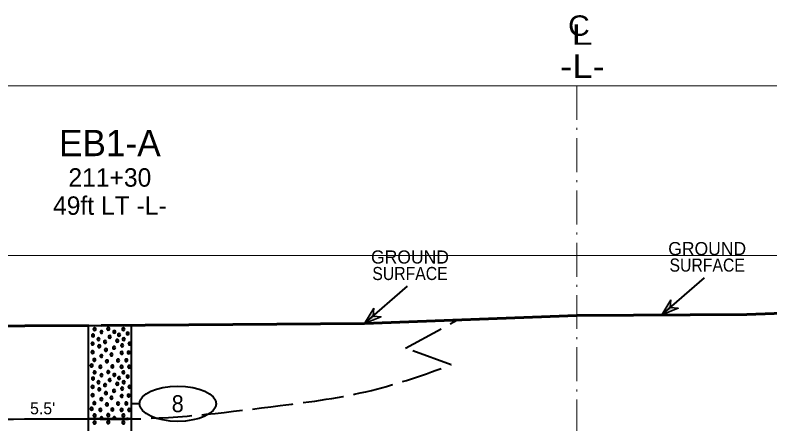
# Model space of a CAD drawing. Extents: x -582 to 653, y -817 to -3.
# Drawn here: x -29.8 to 14.65, y -494.04 to -469.97 of the extents above; entities that cross this region are included whole.
import ezdxf
from ezdxf.enums import TextEntityAlignment as Align

# ---------------------------------------------------------------- set-up
doc = ezdxf.new("R2010")
doc.units = 0
doc.header["$LTSCALE"] = 0.4
doc.linetypes.add('DOT_DASHED', pattern=[7.7, 5, -1.2, 0.3, -1.2])
doc.linetypes.add('LONG_DASHED', pattern=[7.5, 6, -1.5])
for name, color, linetype, lineweight in [('10', 7, 'Continuous', 35), ('26', 7, 'LONG_DASHED', 40), ('27', 7, 'Continuous', 40), ('7', 7, 'Continuous', 13)]:
    doc.layers.add(name, color=color, linetype=linetype, lineweight=lineweight)

msp = doc.modelspace()

# ---------------------------------------------------------------- hatches: boundary and pattern name
at = {"layer": '10'}
for points in [[(8.8165, -486.7304), (8.2789, -487.628), (9.2473, -487.2326), (8.7809, -487.1968)], [(-8.6835, -487.2255), (-9.2211, -488.1231), (-8.2527, -487.7277), (-8.7191, -487.6919)]]:
    msp.add_hatch(color=256, dxfattribs=at).paths.add_polyline_path(points)

# ---------------------------------------------------------------- linework, layer by layer
for points in [[(8.8165, -486.7304), (8.2789, -487.628), (9.2473, -487.2326), (8.7809, -487.1968)], [(-8.6835, -487.2255), (-9.2211, -488.1231), (-8.2527, -487.7277), (-8.7191, -487.6919)]]:
    msp.add_lwpolyline(points, close=True, dxfattribs=at)
at = {"layer": '26', "linetype": 'Continuous', "lineweight": 60}
for points in [[(-9.2213, -488.1228), (3.2787, -487.6628), (13.2787, -487.5928), (20.7787, -487.3328), (27.2787, -487.2128), (33.2787, -486.9428), (43.2787, -486.7528)], [(-24.7213, -488.2528), (-9.2213, -488.1228), (3.2787, -487.6628), (13.2787, -487.5928)], [(-41.7213, -488.2328), (-36.7213, -488.3028), (-25.4713, -488.256)]]:
    msp.add_lwpolyline(points, dxfattribs=at)
at = {"layer": '26'}
msp.add_lwpolyline([(-4.1274, -490.5739), (-6.817, -489.577), (-3.7572, -487.9217)], dxfattribs=at)
msp.add_spline([(-39.7899, -493.8636), (-29.2387, -493.7528), (-25.4713, -493.7528), (-22.9713, -493.7528), (-14.1886, -492.9664), (-8.8094, -492.0692), (-4.1274, -490.5739)], degree=3, dxfattribs=at)
at = {"layer": '27'}
for p, q in [((8.2787, -487.6278), (10.7991, -485.4455)), ((-9.2213, -488.1228), (-6.7009, -485.9405)), ((-22.4714, -492.8528), (-22.9714, -492.8528)), ((-29.2387, -493.7528), (-25.4713, -493.7528))]:
    msp.add_line(p, q, dxfattribs=at)
for points in [[(-25.4713, -488.2528), (-22.9713, -488.2528), (-22.9713, -493.7528), (-25.4713, -493.7528)], [(-25.0394, -488.4655), (-25.0496, -488.4274), (-25.0775, -488.3995), (-25.1156, -488.3893), (-25.1537, -488.3995), (-25.1816, -488.4274), (-25.1918, -488.4655), (-25.1816, -488.5036), (-25.1537, -488.5314), (-25.1156, -488.5417), (-25.0775, -488.5314), (-25.0496, -488.5036)], [(-24.2384, -488.4459), (-24.2487, -488.4078), (-24.2765, -488.3799), (-24.3146, -488.3697), (-24.3527, -488.3799), (-24.3806, -488.4078), (-24.3908, -488.4459), (-24.3806, -488.484), (-24.3527, -488.5119), (-24.3146, -488.5221), (-24.2765, -488.5119), (-24.2487, -488.484)], [(-23.3448, -488.4655), (-23.355, -488.4274), (-23.3829, -488.3995), (-23.421, -488.3893), (-23.4591, -488.3995), (-23.487, -488.4274), (-23.4972, -488.4655), (-23.487, -488.5036), (-23.4591, -488.5315), (-23.421, -488.5417), (-23.3829, -488.5315), (-23.355, -488.5036)], [(-25.1356, -488.8333), (-25.1458, -488.7952), (-25.1737, -488.7673), (-25.2118, -488.7571), (-25.2499, -488.7673), (-25.2778, -488.7952), (-25.288, -488.8333), (-25.2778, -488.8714), (-25.2499, -488.8993), (-25.2118, -488.9095), (-25.1737, -488.8993), (-25.1458, -488.8714)], [(-24.6345, -488.6307), (-24.6447, -488.5926), (-24.6726, -488.5647), (-24.7107, -488.5545), (-24.7488, -488.5647), (-24.7767, -488.5926), (-24.7869, -488.6307), (-24.7767, -488.6688), (-24.7488, -488.6967), (-24.7107, -488.7069), (-24.6726, -488.6967), (-24.6447, -488.6688)], [(-24.1495, -488.9165), (-24.1597, -488.8784), (-24.1876, -488.8505), (-24.2257, -488.8403), (-24.2638, -488.8505), (-24.2917, -488.8784), (-24.3019, -488.9165), (-24.2917, -488.9546), (-24.2638, -488.9825), (-24.2257, -488.9927), (-24.1876, -488.9825), (-24.1597, -488.9546)], [(-23.8794, -488.6217), (-23.8896, -488.5836), (-23.9175, -488.5557), (-23.9556, -488.5455), (-23.9937, -488.5557), (-24.0216, -488.5836), (-24.0318, -488.6217), (-24.0216, -488.6598), (-23.9937, -488.6877), (-23.9556, -488.6979), (-23.9175, -488.6877), (-23.8896, -488.6598)], [(-23.6012, -488.799), (-23.6114, -488.7609), (-23.6393, -488.733), (-23.6774, -488.7228), (-23.7155, -488.733), (-23.7434, -488.7609), (-23.7536, -488.799), (-23.7434, -488.8371), (-23.7155, -488.865), (-23.6774, -488.8752), (-23.6393, -488.865), (-23.6114, -488.8371)], [(-23.0939, -488.7176), (-23.1041, -488.6795), (-23.132, -488.6516), (-23.1701, -488.6414), (-23.2082, -488.6516), (-23.2361, -488.6795), (-23.2463, -488.7176), (-23.2361, -488.7557), (-23.2082, -488.7836), (-23.1701, -488.7938), (-23.132, -488.7836), (-23.1041, -488.7557)], [(-25.1585, -489.3177), (-25.1687, -489.2796), (-25.1966, -489.2517), (-25.2347, -489.2415), (-25.2728, -489.2517), (-25.3007, -489.2796), (-25.3109, -489.3177), (-25.3007, -489.3558), (-25.2728, -489.3837), (-25.2347, -489.3939), (-25.1966, -489.3837), (-25.1687, -489.3558)], [(-24.8127, -489.052), (-24.8229, -489.0139), (-24.8508, -488.986), (-24.8889, -488.9758), (-24.927, -488.986), (-24.9549, -489.0139), (-24.9651, -489.052), (-24.9549, -489.0901), (-24.927, -489.118), (-24.8889, -489.1282), (-24.8508, -489.118), (-24.8229, -489.0901)], [(-24.4211, -489.2134), (-24.4314, -489.1753), (-24.4592, -489.1474), (-24.4973, -489.1372), (-24.5354, -489.1474), (-24.5633, -489.1753), (-24.5735, -489.2134), (-24.5633, -489.2515), (-24.5354, -489.2794), (-24.4973, -489.2896), (-24.4592, -489.2794), (-24.4314, -489.2515)], [(-23.7054, -489.1448), (-23.7156, -489.1067), (-23.7435, -489.0788), (-23.7816, -489.0686), (-23.8197, -489.0788), (-23.8476, -489.1067), (-23.8578, -489.1448), (-23.8476, -489.1829), (-23.8197, -489.2108), (-23.7816, -489.221), (-23.7435, -489.2108), (-23.7156, -489.1829)], [(-23.324, -489.052), (-23.3342, -489.0139), (-23.3621, -488.986), (-23.4002, -488.9758), (-23.4383, -488.986), (-23.4662, -489.0139), (-23.4764, -489.052), (-23.4662, -489.0901), (-23.4383, -489.118), (-23.4002, -489.1282), (-23.3621, -489.118), (-23.3342, -489.0901)], [(-22.9783, -489.3177), (-22.9885, -489.2796), (-23.0164, -489.2517), (-23.0545, -489.2415), (-23.0926, -489.2517), (-23.1204, -489.2796), (-23.1307, -489.3177), (-23.1204, -489.3558), (-23.0926, -489.3837), (-23.0545, -489.3939), (-23.0164, -489.3837), (-22.9885, -489.3558)], [(-25.1585, -489.8135), (-25.1687, -489.7754), (-25.1966, -489.7475), (-25.2347, -489.7373), (-25.2728, -489.7475), (-25.3007, -489.7754), (-25.3109, -489.8135), (-25.3007, -489.8516), (-25.2728, -489.8794), (-25.2347, -489.8897), (-25.1966, -489.8794), (-25.1687, -489.8516)], [(-24.7669, -489.4677), (-24.7771, -489.4296), (-24.805, -489.4017), (-24.8431, -489.3915), (-24.8812, -489.4017), (-24.9091, -489.4296), (-24.9193, -489.4677), (-24.9091, -489.5058), (-24.8812, -489.5337), (-24.8431, -489.5439), (-24.805, -489.5337), (-24.7771, -489.5058)], [(-24.3728, -489.6863), (-24.383, -489.6482), (-24.4109, -489.6203), (-24.449, -489.6101), (-24.4871, -489.6203), (-24.515, -489.6482), (-24.5252, -489.6863), (-24.515, -489.7244), (-24.4871, -489.7523), (-24.449, -489.7625), (-24.4109, -489.7523), (-24.383, -489.7244)], [(-23.8948, -489.5554), (-23.905, -489.5173), (-23.9329, -489.4894), (-23.971, -489.4792), (-24.0091, -489.4894), (-24.037, -489.5173), (-24.0472, -489.5554), (-24.037, -489.5935), (-24.0091, -489.6214), (-23.971, -489.6316), (-23.9329, -489.6214), (-23.905, -489.5935)], [(-23.4168, -489.4219), (-23.4271, -489.3838), (-23.4549, -489.3559), (-23.493, -489.3457), (-23.5311, -489.3559), (-23.559, -489.3838), (-23.5692, -489.4219), (-23.559, -489.46), (-23.5311, -489.4879), (-23.493, -489.4981), (-23.4549, -489.4879), (-23.4271, -489.46)], [(-23.0355, -489.8363), (-23.0457, -489.7982), (-23.0736, -489.7704), (-23.1117, -489.7601), (-23.1498, -489.7704), (-23.1777, -489.7982), (-23.1879, -489.8363), (-23.1777, -489.8744), (-23.1498, -489.9023), (-23.1117, -489.9125), (-23.0736, -489.9023), (-23.0457, -489.8744)], [(-25.0555, -490.2762), (-25.0657, -490.2381), (-25.0936, -490.2102), (-25.1317, -490.2), (-25.1698, -490.2102), (-25.1977, -490.2381), (-25.2079, -490.2762), (-25.1977, -490.3143), (-25.1698, -490.3422), (-25.1317, -490.3524), (-25.0936, -490.3422), (-25.0657, -490.3143)], [(-24.6398, -490.0448), (-24.65, -490.0067), (-24.6779, -489.9788), (-24.716, -489.9686), (-24.7541, -489.9788), (-24.782, -490.0067), (-24.7922, -490.0448), (-24.782, -490.0829), (-24.7541, -490.1108), (-24.716, -490.121), (-24.6779, -490.1108), (-24.65, -490.0829)], [(-24.0449, -489.9609), (-24.0551, -489.9228), (-24.083, -489.8949), (-24.1211, -489.8847), (-24.1592, -489.8949), (-24.187, -489.9228), (-24.1973, -489.9609), (-24.187, -489.999), (-24.1592, -490.0269), (-24.1211, -490.0371), (-24.083, -490.0269), (-24.0551, -489.999)], [(-23.4397, -489.8605), (-23.4499, -489.8224), (-23.4778, -489.7945), (-23.5159, -489.7843), (-23.554, -489.7945), (-23.5819, -489.8224), (-23.5921, -489.8605), (-23.5819, -489.8986), (-23.554, -489.9265), (-23.5159, -489.9367), (-23.4778, -489.9265), (-23.4499, -489.8986)], [(-25.217, -490.6093), (-25.2272, -490.5712), (-25.2551, -490.5433), (-25.2932, -490.5331), (-25.3313, -490.5433), (-25.3592, -490.5712), (-25.3694, -490.6093), (-25.3592, -490.6474), (-25.3313, -490.6753), (-25.2932, -490.6855), (-25.2551, -490.6753), (-25.2272, -490.6474)], [(-24.6983, -490.6792), (-24.7085, -490.6411), (-24.7364, -490.6132), (-24.7745, -490.603), (-24.8126, -490.6132), (-24.8405, -490.6411), (-24.8507, -490.6792), (-24.8405, -490.7173), (-24.8126, -490.7452), (-24.7745, -490.7554), (-24.7364, -490.7452), (-24.7085, -490.7173)], [(-24.3169, -490.3563), (-24.3271, -490.3182), (-24.355, -490.2903), (-24.3931, -490.2801), (-24.4312, -490.2903), (-24.4591, -490.3182), (-24.4693, -490.3563), (-24.4591, -490.3944), (-24.4312, -490.4223), (-24.3931, -490.4325), (-24.355, -490.4223), (-24.3271, -490.3944)], [(-23.994, -490.6563), (-24.0042, -490.6182), (-24.0321, -490.5903), (-24.0702, -490.5801), (-24.1083, -490.5903), (-24.1362, -490.6182), (-24.1464, -490.6563), (-24.1362, -490.6944), (-24.1083, -490.7223), (-24.0702, -490.7325), (-24.0321, -490.7223), (-24.0042, -490.6944)], [(-23.6597, -490.3054), (-23.6699, -490.2673), (-23.6978, -490.2394), (-23.7359, -490.2292), (-23.774, -490.2394), (-23.8018, -490.2673), (-23.8121, -490.3054), (-23.8018, -490.3435), (-23.774, -490.3714), (-23.7359, -490.3816), (-23.6978, -490.3714), (-23.6699, -490.3435)], [(-23.4512, -490.6792), (-23.4614, -490.6411), (-23.4893, -490.6132), (-23.5274, -490.603), (-23.5655, -490.6132), (-23.5934, -490.6411), (-23.6036, -490.6792), (-23.5934, -490.7173), (-23.5655, -490.7452), (-23.5274, -490.7554), (-23.4893, -490.7452), (-23.4614, -490.7173)], [(-23.174, -490.2978), (-23.1842, -490.2597), (-23.2121, -490.2318), (-23.2502, -490.2216), (-23.2883, -490.2318), (-23.3162, -490.2597), (-23.3264, -490.2978), (-23.3162, -490.3359), (-23.2883, -490.3638), (-23.2502, -490.374), (-23.2121, -490.3638), (-23.1842, -490.3359)], [(-23.0011, -490.6792), (-23.0113, -490.6411), (-23.0392, -490.6132), (-23.0773, -490.603), (-23.1154, -490.6132), (-23.1433, -490.6411), (-23.1535, -490.6792), (-23.1433, -490.7173), (-23.1154, -490.7452), (-23.0773, -490.7554), (-23.0392, -490.7452), (-23.0113, -490.7173)], [(-25.0394, -491.0055), (-25.0496, -490.9674), (-25.0775, -490.9395), (-25.1156, -490.9293), (-25.1537, -490.9395), (-25.1816, -490.9674), (-25.1918, -491.0055), (-25.1816, -491.0436), (-25.1537, -491.0714), (-25.1156, -491.0817), (-25.0775, -491.0714), (-25.0496, -491.0436)], [(-24.6345, -491.1707), (-24.6447, -491.1326), (-24.6726, -491.1047), (-24.7107, -491.0945), (-24.7488, -491.1047), (-24.7767, -491.1326), (-24.7869, -491.1707), (-24.7767, -491.2088), (-24.7488, -491.2367), (-24.7107, -491.2469), (-24.6726, -491.2367), (-24.6447, -491.2088)], [(-24.2384, -490.9859), (-24.2487, -490.9478), (-24.2765, -490.9199), (-24.3146, -490.9097), (-24.3527, -490.9199), (-24.3806, -490.9478), (-24.3908, -490.9859), (-24.3806, -491.024), (-24.3527, -491.0519), (-24.3146, -491.0621), (-24.2765, -491.0519), (-24.2487, -491.024)], [(-23.8794, -491.1617), (-23.8896, -491.1236), (-23.9175, -491.0957), (-23.9556, -491.0855), (-23.9937, -491.0957), (-24.0216, -491.1236), (-24.0318, -491.1617), (-24.0216, -491.1998), (-23.9937, -491.2277), (-23.9556, -491.2379), (-23.9175, -491.2277), (-23.8896, -491.1998)], [(-23.3448, -491.0055), (-23.355, -490.9674), (-23.3829, -490.9395), (-23.421, -490.9293), (-23.4591, -490.9395), (-23.487, -490.9674), (-23.4972, -491.0055), (-23.487, -491.0436), (-23.4591, -491.0715), (-23.421, -491.0817), (-23.3829, -491.0715), (-23.355, -491.0436)], [(-25.1356, -491.3733), (-25.1458, -491.3352), (-25.1737, -491.3073), (-25.2118, -491.2971), (-25.2499, -491.3073), (-25.2778, -491.3352), (-25.288, -491.3733), (-25.2778, -491.4114), (-25.2499, -491.4393), (-25.2118, -491.4495), (-25.1737, -491.4393), (-25.1458, -491.4114)], [(-24.8127, -491.592), (-24.8229, -491.5539), (-24.8508, -491.526), (-24.8889, -491.5158), (-24.927, -491.526), (-24.9549, -491.5539), (-24.9651, -491.592), (-24.9549, -491.6301), (-24.927, -491.658), (-24.8889, -491.6682), (-24.8508, -491.658), (-24.8229, -491.6301)], [(-24.1495, -491.4565), (-24.1597, -491.4184), (-24.1876, -491.3905), (-24.2257, -491.3803), (-24.2638, -491.3905), (-24.2917, -491.4184), (-24.3019, -491.4565), (-24.2917, -491.4946), (-24.2638, -491.5225), (-24.2257, -491.5327), (-24.1876, -491.5225), (-24.1597, -491.4946)], [(-23.6012, -491.339), (-23.6114, -491.3009), (-23.6393, -491.273), (-23.6774, -491.2628), (-23.7155, -491.273), (-23.7434, -491.3009), (-23.7536, -491.339), (-23.7434, -491.3771), (-23.7155, -491.405), (-23.6774, -491.4152), (-23.6393, -491.405), (-23.6114, -491.3771)], [(-23.324, -491.592), (-23.3342, -491.5539), (-23.3621, -491.526), (-23.4002, -491.5158), (-23.4383, -491.526), (-23.4662, -491.5539), (-23.4764, -491.592), (-23.4662, -491.6301), (-23.4383, -491.658), (-23.4002, -491.6682), (-23.3621, -491.658), (-23.3342, -491.6301)], [(-23.0939, -491.2576), (-23.1041, -491.2195), (-23.132, -491.1916), (-23.1701, -491.1814), (-23.2082, -491.1916), (-23.2361, -491.2195), (-23.2463, -491.2576), (-23.2361, -491.2957), (-23.2082, -491.3236), (-23.1701, -491.3338), (-23.132, -491.3236), (-23.1041, -491.2957)], [(-25.1585, -491.8577), (-25.1687, -491.8196), (-25.1966, -491.7917), (-25.2347, -491.7815), (-25.2728, -491.7917), (-25.3007, -491.8196), (-25.3109, -491.8577), (-25.3007, -491.8958), (-25.2728, -491.9237), (-25.2347, -491.9339), (-25.1966, -491.9237), (-25.1687, -491.8958)], [(-24.7669, -492.0077), (-24.7771, -491.9696), (-24.805, -491.9417), (-24.8431, -491.9315), (-24.8812, -491.9417), (-24.9091, -491.9696), (-24.9193, -492.0077), (-24.9091, -492.0458), (-24.8812, -492.0737), (-24.8431, -492.0839), (-24.805, -492.0737), (-24.7771, -492.0458)], [(-24.4211, -491.7534), (-24.4314, -491.7153), (-24.4592, -491.6874), (-24.4973, -491.6772), (-24.5354, -491.6874), (-24.5633, -491.7153), (-24.5735, -491.7534), (-24.5633, -491.7915), (-24.5354, -491.8194), (-24.4973, -491.8296), (-24.4592, -491.8194), (-24.4314, -491.7915)], [(-23.7054, -491.6848), (-23.7156, -491.6467), (-23.7435, -491.6188), (-23.7816, -491.6086), (-23.8197, -491.6188), (-23.8476, -491.6467), (-23.8578, -491.6848), (-23.8476, -491.7229), (-23.8197, -491.7508), (-23.7816, -491.761), (-23.7435, -491.7508), (-23.7156, -491.7229)], [(-23.4168, -491.9619), (-23.4271, -491.9238), (-23.4549, -491.8959), (-23.493, -491.8857), (-23.5311, -491.8959), (-23.559, -491.9238), (-23.5692, -491.9619), (-23.559, -492), (-23.5311, -492.0279), (-23.493, -492.0381), (-23.4549, -492.0279), (-23.4271, -492)], [(-22.9783, -491.8577), (-22.9885, -491.8196), (-23.0164, -491.7917), (-23.0545, -491.7815), (-23.0926, -491.7917), (-23.1204, -491.8196), (-23.1307, -491.8577), (-23.1204, -491.8958), (-23.0926, -491.9237), (-23.0545, -491.9339), (-23.0164, -491.9237), (-22.9885, -491.8958)], [(-25.1585, -492.3535), (-25.1687, -492.3154), (-25.1966, -492.2875), (-25.2347, -492.2773), (-25.2728, -492.2875), (-25.3007, -492.3154), (-25.3109, -492.3535), (-25.3007, -492.3916), (-25.2728, -492.4194), (-25.2347, -492.4297), (-25.1966, -492.4194), (-25.1687, -492.3916)], [(-24.3728, -492.2263), (-24.383, -492.1882), (-24.4109, -492.1603), (-24.449, -492.1501), (-24.4871, -492.1603), (-24.515, -492.1882), (-24.5252, -492.2263), (-24.515, -492.2644), (-24.4871, -492.2923), (-24.449, -492.3025), (-24.4109, -492.2923), (-24.383, -492.2644)], [(-24.0449, -492.5009), (-24.0551, -492.4628), (-24.083, -492.4349), (-24.1211, -492.4247), (-24.1592, -492.4349), (-24.187, -492.4628), (-24.1973, -492.5009), (-24.187, -492.539), (-24.1592, -492.5669), (-24.1211, -492.5771), (-24.083, -492.5669), (-24.0551, -492.539)], [(-23.8948, -492.0954), (-23.905, -492.0573), (-23.9329, -492.0294), (-23.971, -492.0192), (-24.0091, -492.0294), (-24.037, -492.0573), (-24.0472, -492.0954), (-24.037, -492.1335), (-24.0091, -492.1614), (-23.971, -492.1716), (-23.9329, -492.1614), (-23.905, -492.1335)], [(-23.4397, -492.4005), (-23.4499, -492.3624), (-23.4778, -492.3345), (-23.5159, -492.3243), (-23.554, -492.3345), (-23.5819, -492.3624), (-23.5921, -492.4005), (-23.5819, -492.4386), (-23.554, -492.4665), (-23.5159, -492.4767), (-23.4778, -492.4665), (-23.4499, -492.4386)], [(-23.0355, -492.3763), (-23.0457, -492.3382), (-23.0736, -492.3104), (-23.1117, -492.3001), (-23.1498, -492.3104), (-23.1777, -492.3382), (-23.1879, -492.3763), (-23.1777, -492.4144), (-23.1498, -492.4423), (-23.1117, -492.4525), (-23.0736, -492.4423), (-23.0457, -492.4144)], [(-25.0555, -492.8162), (-25.0657, -492.7781), (-25.0936, -492.7502), (-25.1317, -492.74), (-25.1698, -492.7502), (-25.1977, -492.7781), (-25.2079, -492.8162), (-25.1977, -492.8543), (-25.1698, -492.8822), (-25.1317, -492.8924), (-25.0936, -492.8822), (-25.0657, -492.8543)], [(-24.6398, -492.5848), (-24.65, -492.5467), (-24.6779, -492.5188), (-24.716, -492.5086), (-24.7541, -492.5188), (-24.782, -492.5467), (-24.7922, -492.5848), (-24.782, -492.6229), (-24.7541, -492.6508), (-24.716, -492.661), (-24.6779, -492.6508), (-24.65, -492.6229)], [(-24.3169, -492.8963), (-24.3271, -492.8582), (-24.355, -492.8303), (-24.3931, -492.8201), (-24.4312, -492.8303), (-24.4591, -492.8582), (-24.4693, -492.8963), (-24.4591, -492.9344), (-24.4312, -492.9623), (-24.3931, -492.9725), (-24.355, -492.9623), (-24.3271, -492.9344)], [(-23.6597, -492.8454), (-23.6699, -492.8073), (-23.6978, -492.7794), (-23.7359, -492.7692), (-23.774, -492.7794), (-23.8018, -492.8073), (-23.8121, -492.8454), (-23.8018, -492.8835), (-23.774, -492.9114), (-23.7359, -492.9216), (-23.6978, -492.9114), (-23.6699, -492.8835)], [(-23.174, -492.8378), (-23.1842, -492.7997), (-23.2121, -492.7718), (-23.2502, -492.7616), (-23.2883, -492.7718), (-23.3162, -492.7997), (-23.3264, -492.8378), (-23.3162, -492.8759), (-23.2883, -492.9038), (-23.2502, -492.914), (-23.2121, -492.9038), (-23.1842, -492.8759)], [(-25.217, -493.1493), (-25.2272, -493.1112), (-25.2551, -493.0833), (-25.2932, -493.0731), (-25.3313, -493.0833), (-25.3592, -493.1112), (-25.3694, -493.1493), (-25.3592, -493.1874), (-25.3313, -493.2153), (-25.2932, -493.2255), (-25.2551, -493.2153), (-25.2272, -493.1874)], [(-24.6983, -493.2192), (-24.7085, -493.1811), (-24.7364, -493.1532), (-24.7745, -493.143), (-24.8126, -493.1532), (-24.8405, -493.1811), (-24.8507, -493.2192), (-24.8405, -493.2573), (-24.8126, -493.2852), (-24.7745, -493.2954), (-24.7364, -493.2852), (-24.7085, -493.2573)], [(-23.994, -493.1963), (-24.0042, -493.1582), (-24.0321, -493.1303), (-24.0702, -493.1201), (-24.1083, -493.1303), (-24.1362, -493.1582), (-24.1464, -493.1963), (-24.1362, -493.2344), (-24.1083, -493.2623), (-24.0702, -493.2725), (-24.0321, -493.2623), (-24.0042, -493.2344)], [(-23.4512, -493.2192), (-23.4614, -493.1811), (-23.4893, -493.1532), (-23.5274, -493.143), (-23.5655, -493.1532), (-23.5934, -493.1811), (-23.6036, -493.2192), (-23.5934, -493.2573), (-23.5655, -493.2852), (-23.5274, -493.2954), (-23.4893, -493.2852), (-23.4614, -493.2573)], [(-23.0011, -493.2192), (-23.0113, -493.1811), (-23.0392, -493.1532), (-23.0773, -493.143), (-23.1154, -493.1532), (-23.1433, -493.1811), (-23.1535, -493.2192), (-23.1433, -493.2573), (-23.1154, -493.2852), (-23.0773, -493.2954), (-23.0392, -493.2852), (-23.0113, -493.2573)], [(-25.4713, -493.7528), (-22.9713, -493.7528), (-22.9713, -499.2528), (-25.4713, -499.2528)], [(-25.0394, -493.5455), (-25.0496, -493.5074), (-25.0775, -493.4795), (-25.1156, -493.4693), (-25.1537, -493.4795), (-25.1816, -493.5074), (-25.1918, -493.5455), (-25.1816, -493.5836), (-25.1537, -493.6114), (-25.1156, -493.6217), (-25.0775, -493.6114), (-25.0496, -493.5836)], [(-24.6447, -493.7488), (-24.6345, -493.7107), (-24.6447, -493.6726), (-24.6726, -493.6447), (-24.7107, -493.6345), (-24.7488, -493.6447), (-24.7767, -493.6726), (-24.7869, -493.7107), (-24.7767, -493.7488), (-24.7727, -493.7528), (-24.6487, -493.7528)], [(-24.2384, -493.5259), (-24.2487, -493.4878), (-24.2765, -493.4599), (-24.3146, -493.4497), (-24.3527, -493.4599), (-24.3806, -493.4878), (-24.3908, -493.5259), (-24.3806, -493.564), (-24.3527, -493.5919), (-24.3146, -493.6021), (-24.2765, -493.5919), (-24.2487, -493.564)], [(-23.8896, -493.7398), (-23.8794, -493.7017), (-23.8896, -493.6636), (-23.9175, -493.6357), (-23.9556, -493.6255), (-23.9937, -493.6357), (-24.0216, -493.6636), (-24.0318, -493.7017), (-24.0216, -493.7398), (-24.0086, -493.7528), (-23.9026, -493.7528)], [(-23.3448, -493.5455), (-23.355, -493.5074), (-23.3829, -493.4795), (-23.421, -493.4693), (-23.4591, -493.4795), (-23.487, -493.5074), (-23.4972, -493.5455), (-23.487, -493.5836), (-23.4591, -493.6115), (-23.421, -493.6217), (-23.3829, -493.6115), (-23.355, -493.5836)], [(-23.132, -493.7316), (-23.1701, -493.7214), (-23.2082, -493.7316), (-23.2294, -493.7528), (-23.1108, -493.7528)], [(-25.0394, -493.9655), (-25.0496, -493.9274), (-25.0775, -493.8995), (-25.1156, -493.8893), (-25.1537, -493.8995), (-25.1816, -493.9274), (-25.1918, -493.9655), (-25.1816, -494.0036), (-25.1537, -494.0314), (-25.1156, -494.0417), (-25.0775, -494.0314), (-25.0496, -494.0036)], [(-24.2384, -493.9459), (-24.2487, -493.9078), (-24.2765, -493.8799), (-24.3146, -493.8697), (-24.3527, -493.8799), (-24.3806, -493.9078), (-24.3908, -493.9459), (-24.3806, -493.984), (-24.3527, -494.0119), (-24.3146, -494.0221), (-24.2765, -494.0119), (-24.2487, -493.984)], [(-23.3448, -493.9655), (-23.355, -493.9274), (-23.3829, -493.8995), (-23.421, -493.8893), (-23.4591, -493.8995), (-23.487, -493.9274), (-23.4972, -493.9655), (-23.487, -494.0036), (-23.4591, -494.0315), (-23.421, -494.0417), (-23.3829, -494.0315), (-23.355, -494.0036)]]:
    msp.add_lwpolyline(points, close=True, dxfattribs=at)
msp.add_ellipse((-20.214, -492.8528), major_axis=(2.2574, 0), ratio=0.461538, dxfattribs=at)
at = {"layer": '7'}
for p, q in [((-62.9147, -474.1328), (28.379, -474.1328)), ((-23.9857, -474.1328), (67.308, -474.1328)), ((-62.9147, -484.1328), (28.379, -484.1328)), ((-23.9857, -484.1328), (67.308, -484.1328))]:
    msp.add_line(p, q, dxfattribs=at)
at = {"layer": '7', "linetype": 'DOT_DASHED'}
msp.add_line((3.2787, -474.1328), (3.2787, -611.8952), dxfattribs=at)
msp.add_line((3.2787, -474.1328), (3.2787, -611.8952), dxfattribs=at)

# ---------------------------------------------------------------- texts
at = {"layer": '27'}
for s, width, p in [('C', 1.1, (2.7624, -471.1833)), ('C', 1.1, (2.7625, -471.1834)), ('L', 1.4, (2.9588, -471.7167)), ('L', 1.4, (2.9589, -471.7168))]:
    msp.add_text(s, height=1.2, dxfattribs=dict(at, width=width)).set_placement(p)
for s, height, width, p in [('-L-', 1.4, 1.15, (3.6052, -473.6753)), ('-L-', 1.4, 1.15, (3.6053, -473.6754)), ('SURFACE', 0.7718, 0.9, (10.9529, -485.0759)), ('SURFACE', 0.7718, 0.9, (-6.547, -485.5712)), ('8', 1, 0.95, (-20.2212, -493.3528))]:
    msp.add_text(s, height=height, dxfattribs=dict(at, width=width)).set_placement(p, align=Align.CENTER)
for s, height, p in [('EB1-A', 1.55, (-24.2196, -478.2751)), ('211+30', 1.085, (-24.2187, -480.0715)), ('49ft LT -L-', 1.085, (-24.2191, -481.7285)), ('GROUND', 0.7718, (10.9528, -484.1041)), ('GROUND', 0.7718, (-6.547, -484.5994))]:
    msp.add_text(s, height=height, dxfattribs=at).set_placement(p, align=Align.CENTER)
msp.add_text("5.5'", height=0.6976, dxfattribs=at).set_placement((-28.9146, -493.4764))

doc.saveas('drawing.dxf')
